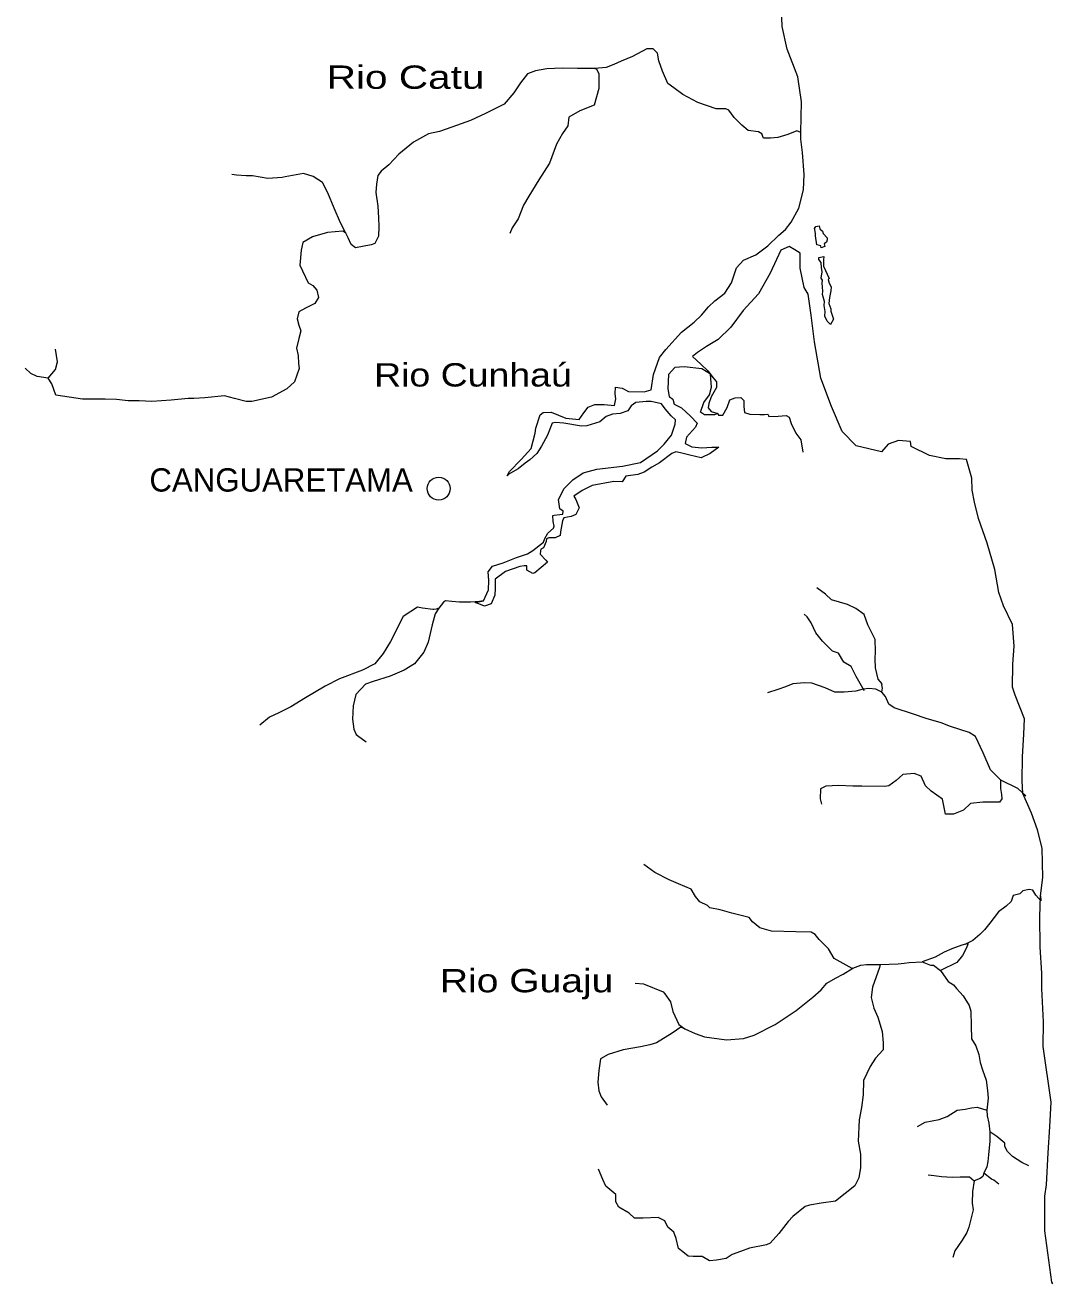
# Model space of a CAD drawing. Extents: x 47169 to 972804, y 7447977 to 9608469.
# Drawn here: x 916285 to 946261, y 9269921 to 9306596 of the extents above; entities that cross this region are included whole.
import ezdxf

# ---------------------------------------------------------------- set-up
doc = ezdxf.new("R2010")
doc.units = 0
doc.header["$LTSCALE"] = 270
doc.layers.add('1', color=7, linetype='Continuous', lineweight=13)
doc.layers.add('2', color=7, linetype='Continuous', lineweight=13)
doc.layers.add('3', color=7, linetype='Continuous')

msp = doc.modelspace()

# ---------------------------------------------------------------- linework, layer by layer
at = {"layer": '1'}
for points in [[(931402.4, 9291518.7), (931444.2, 9291622.5), (931526.3, 9291781.5), (931697, 9291924.2), (931714.1, 9291988.3), (931684, 9292117.1), (931678.7, 9292294.4), (931711, 9292301.9), (931879.6, 9292323.9), (931967.2, 9292331), (931976.8, 9292427.3), (931882, 9292493.4), (931838.6, 9292767.5), (932011.8, 9293086.4), (932255.3, 9293340.5), (932562.9, 9293545.3), (932707.3, 9293584.1), (932964.9, 9293644.2), (933710.6, 9293738.3), (934232.4, 9293844), (934725, 9294182.7), (934920.5, 9294381.7), (935140.8, 9294636), (935249.8, 9294964.3), (935259.6, 9295085), (935126.3, 9295199), (934953.8, 9295410.9), (934844.1, 9295556.9), (934548.6, 9295617.8), (934396.7, 9295620.1), (934100.5, 9295591.3), (933962.3, 9295497.1), (933864.7, 9295344.9), (933639.1, 9295275.7), (933415, 9295247.5), (933229.4, 9295185.8), (933043, 9295027.6), (932673, 9294911.8), (932513.3, 9294905.3), (931994, 9294985.7), (931754.8, 9295013), (931658.1, 9294990.4), (931516.9, 9294638), (931343.8, 9294318), (931212.4, 9294103), (931009.3, 9293920.5), (930871.1, 9293818.5), (930669.2, 9293660.5), (930370.8, 9293487.7), (930346.2, 9293455.8), (930411.5, 9293583.8), (930753.3, 9293932.5), (931046.2, 9294250.5), (931158.2, 9294699.5), (931183.7, 9294843.3), (931310.7, 9295228), (931391.1, 9295299.4), (931631.7, 9295312), (932052.8, 9295137), (932443.8, 9295099.7), (932583.8, 9295290.4), (932706, 9295457.9), (932899.4, 9295536.2), (933171, 9295531.9), (933474.6, 9295504.1), (933510.4, 9295696.7), (933496, 9295840.8), (933507.5, 9296042.4), (933699, 9296007.7), (933881.2, 9295916.6), (934345.6, 9295901.9), (934546.8, 9295963.6), (934617.7, 9296405.2), (934785.6, 9296901.4), (934973.6, 9297132.7), (935429.8, 9297641.1), (935802.3, 9297933.1), (936013.4, 9298139.8), (936217, 9298377.6), (936404.6, 9298560.1), (936695.7, 9298781.7), (936885.4, 9299085), (937036.1, 9299517.1), (937239.6, 9299739.4), (937594.5, 9299902.9), (937950.2, 9300164), (938267.4, 9300472.9), (938462.7, 9300639.9), (938626.2, 9300854.7), (938848.9, 9301261.9), (938992.6, 9301790.5), (939008.2, 9302241.4), (938963.2, 9302877.8), (938913, 9303272.7), (938907.8, 9303465.5), (938930.1, 9304358.5), (938822.5, 9305084), (938507, 9305892), (938365.6, 9306554.6), (938350.8, 9307085.5)], [(938907.8, 9303465.5), (938797.3, 9303515.1), (938531.4, 9303406.3), (938241.4, 9303322.1), (938025, 9303300.4), (937817.7, 9303303.1), (937770.9, 9303424.2), (937676, 9303482.6), (937372.5, 9303519.2), (937190.8, 9303682.4), (936970.7, 9303902.4), (936813.7, 9304114.1), (936726.4, 9304155.7), (936439.2, 9304159), (935905, 9304335.9), (935468.9, 9304575.2), (935208.7, 9304772.2), (935026.6, 9304894.3), (934871.9, 9305251.2), (934764.4, 9305557.8), (934728.3, 9305776.4), (934602.9, 9305905.8), (934418.8, 9305908.3), (933999.1, 9305681), (933668.8, 9305549.4), (933458.5, 9305447.9), (933233.9, 9305362.1), (932904.3, 9305326.8), (932401, 9305332.8), (931945.3, 9305339.5), (931505, 9305321.8), (931175.3, 9305262.2), (930941.8, 9305176.4), (930738, 9304914.2), (930540.8, 9304626.4), (930255.6, 9304292.8), (929715.8, 9304018.7), (929279.7, 9303815.9), (928732.7, 9303621.6), (928370.4, 9303498), (928049.4, 9303421.7), (927614.1, 9303178.9), (927183.6, 9302830.9), (926890.8, 9302520.6), (926672.2, 9302339.4), (926573.7, 9302211.6), (926529.7, 9301954.9), (926517.9, 9301713.4), (926576, 9301318.6), (926594.5, 9300980.5), (926598.2, 9300723.4), (926593.9, 9300442), (926486.9, 9300225.7), (926381.3, 9300186.6), (925924, 9300104.6), (925790.6, 9300203.1), (925705.5, 9300389.9), (925635.5, 9300526.7), (925480.3, 9300827), (925302.9, 9301263.7), (925109.9, 9301708.3), (924962.5, 9302008.6), (924685.5, 9302181.2), (924406.8, 9302273), (923869.4, 9302168.4), (923780.6, 9302153.5), (923364.7, 9302126.7), (922917.3, 9302197.5), (922733.3, 9302200), (922454.1, 9302219.8), (922317.9, 9302237.4)], [(932904.3, 9305326.8), (932953.1, 9305325.4), (933014.1, 9305179.8), (933015.3, 9304753.2), (932879.7, 9304264.4), (932460.5, 9304093.6), (932146.5, 9303913.1), (932118, 9303664), (931962.2, 9303440.2), (931781.3, 9303121.4), (931580.9, 9302568.8), (931269.1, 9302082.5), (930972.9, 9301612.7), (930824.6, 9301349), (930666.4, 9300949.1), (930485.9, 9300685.6), (930419.2, 9300517.7)], [(925635.5, 9300526.7), (925556.2, 9300584.9), (925108, 9300550.5), (924665.9, 9300427.5), (924383.1, 9300262.3), (924339.3, 9300029.9), (924300.6, 9299595.9), (924540.6, 9299077.8), (924675.3, 9299003.7), (924792.9, 9298865.4), (924845.7, 9298655.6), (924730.2, 9298480.3), (924464.3, 9298347.1), (924270.6, 9298236.7), (924219.2, 9298036.5), (924264.4, 9297843.4), (924326.3, 9297681.2), (924265.9, 9297456.7), (924197.3, 9297176.9), (924250.1, 9296966), (924262.8, 9296733.2), (924276.1, 9296588), (924142.4, 9296195.7), (923922.5, 9295990.1), (923470.7, 9295746.4), (922901.1, 9295617.7), (922732.6, 9295620), (922390.8, 9295713.4), (922095.4, 9295789.8), (921526.2, 9295725.3), (921206.9, 9295705.5), (921038.4, 9295707.8), (920541.4, 9295658.3), (919981.4, 9295624.8), (919613.5, 9295638.6), (919293.2, 9295643.1), (918949.9, 9295680), (918622.9, 9295684.6), (917959, 9295692.8), (917185.1, 9295808.1), (917062.3, 9296139.1), (916952.6, 9296301.7), (916633.8, 9296355), (916450.4, 9296437.2), (916285.2, 9296592.4)], [(946261.4, 9269891.2), (946229.6, 9269939.1), (946023.4, 9271439.1), (946023.8, 9272445.4), (946077.5, 9272781.8), (946124.9, 9273714.6), (946177.5, 9274470), (946213.2, 9275185.6), (945975.7, 9276814.3), (945988.1, 9277530.2), (945940.5, 9278504.7), (945939.6, 9278946.9), (945888.1, 9279713), (945878.5, 9280605.2), (945891.9, 9280887.7), (945896.7, 9281209.1), (945969.6, 9281739.3), (945952, 9282591.7), (945816.6, 9283133.6), (945640.9, 9283618.1), (945386, 9284193.1), (945367.9, 9284563.4), (945372.3, 9285263.7), (945415.2, 9285922.8), (945437.6, 9286364.8), (945161.5, 9287060.7), (945085.7, 9287287.3), (945096.5, 9287963.3), (945137.2, 9288484.9), (945083.5, 9289121.5), (944820.5, 9289664.3), (944682.8, 9290052.2), (944573.8, 9290722.4), (944345.9, 9291489.9), (944094.3, 9292208.9), (943973.9, 9292685.2), (943907.8, 9293032.6), (943897.3, 9293386.2), (943738.5, 9293928.2), (943538, 9293946.4), (943137.8, 9293952.8), (942667.3, 9294047.3), (942128.4, 9294313.1), (942114, 9294457.2), (941762.7, 9294486.5), (941457, 9294378.1), (941261.3, 9294155.8), (940519.8, 9294327.7), (940119.5, 9294750.8), (939802.4, 9295471.3), (939496.2, 9296304.8), (939313.6, 9297361.1), (939214.2, 9298135.3), (939120.2, 9298747.7), (939003.1, 9298942.5), (938892.1, 9299507.4), (938891, 9299949.6), (938733.1, 9300040.5), (938566.5, 9300139.3), (938323.9, 9300030.3), (938017.3, 9299366.7), (937672.3, 9298759.9), (937231.8, 9298275.7)], [(937231.8, 9298275.7), (936864.4, 9297789.8), (936498, 9297424.7), (936158.3, 9297227.8), (936013.5, 9297125.9), (935892, 9297047), (935753.7, 9296936.2), (935998.1, 9296707.1), (936195.1, 9296519.5), (936352, 9296308.9), (936454.2, 9296193.9), (936451.9, 9296025.5), (936294.6, 9295754.2), (936227.7, 9295561.8), (936210.1, 9295433.4), (936295.8, 9295327.5), (936487.1, 9295268.4), (936390.3, 9295229.3), (936102.1, 9295233.7), (935984.1, 9295307.7), (936083.8, 9295588.4), (936248.5, 9295818.8), (936307.8, 9296035.5), (936274.1, 9296413.6), (936020.3, 9296570.7), (935509.7, 9296634.4), (935236.8, 9296613.2), (935049, 9296407.4), (935034.7, 9295988.7), (935070.8, 9295771.2), (935174.4, 9295689.5), (935219.8, 9295544), (935434.1, 9295436), (935693.8, 9295191.4), (935883, 9294987.2), (935841.1, 9294875.6), (935571.7, 9294581.8), (935537, 9294397), (935735.8, 9294298), (936022.7, 9294269.2), (936311.1, 9294289.1), (936455.2, 9294288), (936519.5, 9294286.4), (936268.7, 9294105.5), (936002.8, 9293980.1), (935675.2, 9294056.8), (935404.1, 9294125.4), (935261.3, 9294152), (935147.9, 9294105.2), (934792.2, 9293836.4), (934566.1, 9293703), (934338.9, 9293560.7), (934154.3, 9293491.1), (933801.4, 9293439.5), (933702.7, 9293279.6), (933455.5, 9293283.7), (932821.7, 9293172.2), (932531.2, 9293022.6), (932288.3, 9292864.9), (932343, 9292760.3), (932443.1, 9292516.9), (932351.8, 9292325.9), (932215.1, 9292271.5), (931997.5, 9292225.5), (931956.9, 9292138.3), (931903.5, 9291825.1), (931893.8, 9291712.2), (931740.3, 9291642.4), (931564.1, 9291644.9), (931491.8, 9291613.3), (931482.4, 9291541.3), (931407.8, 9291356.9), (931327.7, 9291317.6), (931318.4, 9291262.3), (931308.9, 9291173.7), (931473.8, 9290994), (931521, 9290937.2), (931156.2, 9290628.6), (931091.7, 9290605.8), (930917.3, 9290704.6), (930919.4, 9290825.4), (930839.6, 9290826), (930710.9, 9290811.5), (930300.7, 9290665), (929993.1, 9290443.5), (929996.6, 9290178.7), (929986.2, 9289977.1), (929877.9, 9289720.8), (929684.5, 9289651.4), (929565.2, 9289701.1), (929413.8, 9289759.8), (929654.6, 9289804.5), (929795.6, 9290124.8), (929808.8, 9290398.4), (929788.5, 9290655.6), (929919.5, 9290823), (930232.8, 9290914.8), (930619.7, 9291070.3), (930933.1, 9291178.8), (931094.6, 9291272.8), (931402.4, 9291518.7)], [(916952.6, 9296301.7), (917172.8, 9296556), (917232.1, 9296780.5), (917166, 9297143.2)], [(936487.1, 9295268.4), (936510, 9295220.6), (936638.6, 9295218.5), (936762.3, 9295450.3), (936837.1, 9295665.8), (936998.4, 9295727.7), (937159.2, 9295734.2), (937245, 9295652.7), (937250.3, 9295475.4), (937271.1, 9295297.9), (937422.7, 9295255.8), (937710.8, 9295243.6), (937847.2, 9295241.4), (937951.5, 9295248.4), (937966.7, 9295216.1), (937974.2, 9295183.9), (938246, 9295196.2), (938486.6, 9295208.8), (938566.1, 9295167.2), (938626.8, 9294981.7), (938766.5, 9294698), (938914.7, 9294503), (938972.9, 9294147.9)], [(941274.4, 9287147.7), (941293.1, 9287260.6), (941270.5, 9287357.2), (941287.4, 9287389.2), (941168.8, 9287527.5), (941085.9, 9287850.6), (941082.5, 9288116.6), (941086.4, 9288333.8), (941075.8, 9288679.6), (940867.4, 9289109), (940760, 9289407.9), (940515.2, 9289580.5), (940268.9, 9289704.3), (939806.6, 9289839.7), (939633.8, 9290002.9), (939372.5, 9290184.4)], [(929654.6, 9289804.5), (929534.8, 9289789.9), (929270.8, 9289769.8), (928958.3, 9289774.3), (928734.5, 9289793.8), (928550.6, 9289804), (928486.1, 9289772.4), (928356.2, 9289597.2), (928240.8, 9289430.8), (928156.3, 9289110.1), (928036.1, 9288604.6), (927918.7, 9288316.3), (927641.2, 9287975), (927342.7, 9287785.5), (926932.4, 9287614.7), (926433.6, 9287460), (926208, 9287375.3), (925932, 9287081.5), (925854.1, 9286744.2), (925832.3, 9286358.8), (925875.6, 9286068.2), (925944.2, 9285907), (925976.1, 9285882.4), (926229.7, 9285701)], [(928356.2, 9289597.2), (928275, 9289566.8), (928210.6, 9289551.8), (928178.5, 9289552), (927876.2, 9289596.4), (927724.6, 9289621.9), (927312.4, 9289346.9), (926940, 9288619.5), (926726.8, 9288268.8), (926481.8, 9287974.8), (926126.8, 9287785.8), (925458.8, 9287538.2), (925039.3, 9287318.7), (924458.2, 9286980.7), (924038.5, 9286721.3), (923683.6, 9286541.1), (923410, 9286415.8), (923133.4, 9286186.3)], [(940724.2, 9287236.2), (940756, 9287196.1), (940522, 9287601.3), (940375.7, 9287892.7), (940169.4, 9288024), (940014, 9288284.5), (939838.2, 9288343.5), (939546.7, 9288628.3), (939351.2, 9288872.5), (939211.6, 9289163.9), (939094.4, 9289343.3), (939008.5, 9289417.1)], [(945386, 9284193.1), (945473, 9284119.3), (945244.2, 9284340.5), (944745, 9284580.5), (944438.1, 9284882.1), (944230.3, 9285375.8), (944005.7, 9285854.1), (943816, 9285969.7), (943274.2, 9286145.8), (943004.5, 9286254.3), (942566.5, 9286373), (942192.8, 9286507.8), (941635.5, 9286683.9), (941476.8, 9286799.3), (941376.5, 9287018.4), (941274.4, 9287147.7), (941099.9, 9287231.1), (940892.8, 9287250.4), (940724.2, 9287236.2), (940515.3, 9287174.7), (940171.4, 9287147.4), (939906.5, 9287142.8), (939621.5, 9287275.8), (939231.3, 9287410.7), (939007.4, 9287421.3), (938679, 9287386.2), (938461.1, 9287300.4), (938244.3, 9287223.4), (937938.7, 9287122.7)], [(944745, 9284580.5), (944736.1, 9284572.8), (944733.1, 9284331.2), (944761.7, 9284161.5), (944776.2, 9284032.8), (944702.3, 9283937), (944222.3, 9283936.3), (943861.7, 9283901.5), (943658.4, 9283702.5), (943360.4, 9283586.3), (943128.8, 9283589.2), (943039.1, 9284025.5), (942715, 9284255.2), (942542.2, 9284410.6), (942419.2, 9284694.1), (942220.2, 9284768.8), (941883, 9284741.6), (941688.8, 9284568), (941478.1, 9284417.8), (941358.2, 9284395.5), (940694.3, 9284405.1), (940430.5, 9284408.3), (940013.8, 9284422.6), (939637.9, 9284403.4), (939484.3, 9284324.8), (939472.1, 9284035.7), (939509.7, 9283882.5)], [(940430.9, 9279098.1), (940406.4, 9279082.7), (939883.4, 9279379.4), (939712.7, 9279663.3), (939444.4, 9279932.5), (939327, 9280079.7), (939207.8, 9280146), (938760, 9280151.7), (938057.5, 9280178.3), (937714.7, 9280270.7), (937501, 9280443.1), (937400, 9280573.5), (936897.8, 9280701.5), (936555, 9280794), (936252.9, 9280855), (936189.1, 9280919.8), (935967.2, 9281035.7), (935834.3, 9281190.7), (935709.6, 9281402.2), (935343.9, 9281551.3), (935066.7, 9281676.5), (934653.8, 9281891.3), (934329.7, 9282121)], [(945896.7, 9281209.1), (945911, 9281063.8), (945761.6, 9281226.8), (945676.2, 9281372.6), (945572.2, 9281390.1), (945387.9, 9281352.8), (945298.5, 9281265.9), (945105.3, 9281219.8), (945046.2, 9281044.1), (944900, 9280908.9), (944673.6, 9280743.4), (944420.5, 9280409.6), (944264.8, 9280210.2), (944134.1, 9280075), (943923.2, 9279901.6), (943714, 9279800.2), (943609.6, 9279768.8), (943319.4, 9279660.3), (943093.7, 9279566.8), (942827.6, 9279418.2), (942449.6, 9279278.2)], [(943714, 9279800.2), (943786.3, 9279830.6), (943786, 9279798.5), (943744.1, 9279686.9), (943628.2, 9279462.8), (943464.8, 9279264.7), (942981.9, 9279030.2)], [(941226.4, 9279208.2), (941207, 9279119.6), (941005.1, 9278542.8), (940960.6, 9278238.4), (941043.5, 9277930.8), (941158.9, 9277663.9), (941280.8, 9277251.8), (941314.8, 9276921.3), (941310.9, 9276711.9), (941084.1, 9276474.3), (940928, 9276227.3), (940736.4, 9275818.8), (940729.8, 9275401.1), (940683.6, 9275031.4), (940614.3, 9274678.4), (940587.2, 9274051.4), (940652.8, 9273671.9), (940646.5, 9273286.3), (940601.9, 9272980.8), (940485.9, 9272749), (939919.4, 9272299.2), (939502.2, 9272240.5), (939164.8, 9272181.1), (939037.1, 9272142.2), (938680.2, 9271858), (938541.6, 9271707.3), (938271.7, 9271357.1), (938019.1, 9271078.7), (937906.8, 9271032), (937417.3, 9270935), (937151.7, 9270834), (936910.5, 9270748.4), (936732.3, 9270631.2), (936451.5, 9270578.1), (936243.1, 9270565.3), (936030.2, 9270688.9), (935765.3, 9270693.2), (935622.5, 9270703.2), (935463.9, 9270825.2), (935338.3, 9270923.7), (935278.6, 9271214.5), (935210.2, 9271400.1), (935028.5, 9271540), (934943.5, 9271725.8), (934752.6, 9271825.9), (934312.5, 9271807.2), (934056.5, 9271811.4), (933899.2, 9271950), (933605.8, 9272130.7), (933512.8, 9272285.5), (933516.7, 9272494.9), (933224.9, 9272739.8), (933140, 9272934.4), (933008.3, 9273233.5)], [(934081.2, 9278656.9), (934320.4, 9278637.3), (934892.7, 9278404.6), (934947.7, 9278347.6), (935112.1, 9278111.4), (935179.8, 9277837.2), (935348.6, 9277456.9), (935530.4, 9277325.9), (935833.1, 9277192.7), (936102.7, 9277092), (936741.5, 9277010.5), (937238.3, 9277043.2), (937551.6, 9277143.8), (938164.7, 9277449.3), (938778.6, 9277858.9), (939257.1, 9278246.3), (939508.2, 9278468.1), (939671.6, 9278658.6), (939922.1, 9278807.3), (940148, 9278917.5), (940430.9, 9279098.1), (940656.6, 9279183.8), (940824.1, 9279205.8), (941224.3, 9279208.2), (941753.1, 9279223.9), (941920.6, 9279238.1), (942073.7, 9279260.2), (942449.6, 9279278.2), (942688.3, 9279186.6), (942775.8, 9279185.9), (942981.9, 9279030.2), (943207.6, 9278704.9), (943366.5, 9278613.8), (943452.1, 9278500.1), (943648.8, 9278288), (943820.5, 9278004.1), (943873.6, 9277842.9), (943882.4, 9277416.2), (943892.6, 9277037.1), (944017.4, 9276834.4), (944100.7, 9276575.6), (944145.4, 9276350.2), (944213.5, 9276131.4), (944319.7, 9275832.4), (944355, 9275526.3), (944375.3, 9275301.2), (944338.2, 9274955.7), (944342.4, 9274786.1), (944395, 9274576.2), (944423, 9274326.7), (944418.5, 9274053), (944379.8, 9273651), (944369.4, 9273458.3), (944333.9, 9273305.6), (944251.4, 9273114.6), (944217.4, 9273018.4), (944144.9, 9272962.5), (943968.1, 9272893), (943914.6, 9272579.8), (943908.6, 9272241.8), (943938.1, 9272048.8), (943808.8, 9271543.4), (943751.1, 9271390.9), (943619.6, 9271168.1), (943397.7, 9270857.4), (943346.2, 9270657.2)], [(935530.4, 9277325.9), (935410.7, 9277371.9), (935160.4, 9277201.3), (934700.5, 9276919), (934507.2, 9276865.1), (934235.2, 9276804.1), (933729.2, 9276715), (933287, 9276576.6), (933068.8, 9276450.8), (933015.2, 9276113.3), (932993.8, 9275776.6), (933013.9, 9275518.3), (933083.5, 9275340.5), (933263.4, 9275105.2)], [(942313.9, 9274477.6), (942539.9, 9274603.2), (942941.8, 9274685.4), (943183, 9274771), (943465.9, 9274951.6), (943699, 9274988.5), (943891, 9275025.8), (944050.7, 9275040), (944338.2, 9274955.7)], [(945558.7, 9273329), (945360, 9273428.2), (945083.3, 9273608.8), (944941.4, 9273747.4), (944863.9, 9273894.3), (944858, 9273990.7), (944629.1, 9274186.5), (944423, 9274326.7)], [(942627.5, 9273073.3), (942802.3, 9273046.4), (943010.5, 9273019.2), (943321.8, 9273006.8), (943553.5, 9273011.6), (943745.3, 9273016.7), (943833.9, 9273016), (943968.1, 9272893)], [(944685.5, 9272794.1), (944535.8, 9272917.2), (944472.8, 9272942.1), (944251.4, 9273114.6)]]:
    msp.add_lwpolyline(points, dxfattribs=at)
for points in [[(939339.4, 9300450.3), (939341, 9300514.6), (939318.7, 9300635.6), (939311.2, 9300667.8), (939343.7, 9300724), (939440.4, 9300746.6), (939463, 9300657.7), (939541.1, 9300584), (939565, 9300519.5), (939675, 9300397.9), (939681.1, 9300332.5), (939656.3, 9300268.4), (939591.6, 9300221.2), (939606.5, 9300141.4), (939502, 9300102.2), (939494.7, 9300158.8), (939375.2, 9300191.9)], [(939735.7, 9299206.2), (939703.3, 9299174.3), (939733.6, 9299076.6), (939796, 9298963.1), (939785.1, 9298843.5), (939742.6, 9298658.7), (939723.5, 9298481.6), (939785.5, 9298320.4), (939783.9, 9298256.2), (939859.7, 9298021.8), (939777.5, 9297861.7), (939675.2, 9297960), (939613.1, 9298105.7), (939624.1, 9298241.9), (939594.5, 9298419.4), (939596.4, 9298532.4), (939543.7, 9298742.3), (939553.3, 9298838.6), (939532.9, 9299071.5), (939542.5, 9299160.1), (939503, 9299216.8), (939531, 9299401.7), (939508.7, 9299530.4), (939503.2, 9299675.6), (939432.9, 9299764.8), (939433.3, 9299821.3), (939577.7, 9299851.2), (939575.8, 9299754.8), (939573.3, 9299569.8)]]:
    msp.add_lwpolyline(points, close=True, dxfattribs=at)
at = {"layer": '2'}
msp.add_circle((928348.1, 9293080.8), 332.9, dxfattribs=at)

# ---------------------------------------------------------------- texts
at = {"layer": '3'}
for s, height, width, p in [('Rio Catu', 680.5, 1.3, (925080.4, 9304739)), ('Rio Cunhaú', 680.4, 1.2, (926463.2, 9296057.8)), ('Rio Guaju', 680.2, 1.25, (928384.1, 9278393.2))]:
    msp.add_text(s, height=height, dxfattribs=dict(at, width=width)).set_placement(p)
msp.add_text('CANGUARETAMA', height=680.3, dxfattribs=at).set_placement((919909.8, 9292994.2))

doc.saveas('drawing.dxf')
